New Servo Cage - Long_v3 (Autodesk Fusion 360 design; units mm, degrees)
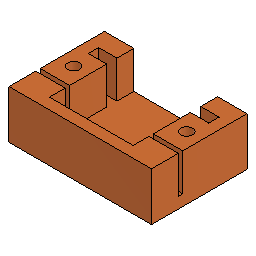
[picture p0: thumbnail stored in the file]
sketch "Sketch1" plane through (0, 0, 0) normal (0, 0, 1) x axis (1, 0, 0)
  line L1 (-14.4, -13) -> (14.4, -13)
  line L2 (-14.4, 13) -> (-14.4, -13)
  line L3 (14.4, 13) -> (-14.4, 13)
  line L4 (14.4, -13) -> (14.4, 13)
  line L5 (-14.4, 13) -> (14.4, -13)
  line L6 (14.4, 13) -> (-14.4, -13)
  line L7 (20.788, 7) -> (-24.9538, 7)
  line L8 (0, 13) -> (0, 0)
  line L9 (-19.4, 5.6) -> (19.4, 5.6)
  line L10 (-19.4, 8.4) -> (-19.4, 5.6)
  line L11 (19.4, 8.4) -> (-19.4, 8.4)
  line L12 (19.4, 5.6) -> (19.4, 8.4)
  line L13 (-19.4, 8.4) -> (19.4, 5.6)
  line L14 (19.4, 8.4) -> (-19.4, 5.6)
  line L15 (19.4, 5.6) -> (-19.4, 5.6)
  line L16 (19.4, 0.6) -> (19.4, 5.6)
  line L17 (-19.4, 0.6) -> (19.4, 0.6)
  line L18 (-19.4, 5.6) -> (-19.4, 0.6)
  line L19 (-19.4, 0) -> (0, 0)
  line L20 (19.4, 8.4) -> (-19.4, 8.4)
  line L21 (19.4, 11.4) -> (19.4, 8.4)
  line L22 (-19.4, 11.4) -> (19.4, 11.4)
  line L23 (-19.4, 8.4) -> (-19.4, 11.4)
  line L24 (-16.4, 0.6) -> (-16.4, 11.4)
  line L25 (16.4, 0.6) -> (16.4, 11.4)
  line L26 (11.4, 13) -> (-11.4, 13)
  line L27 (11.4, -10) -> (11.4, 13)
  line L28 (-11.4, -10) -> (11.4, -10)
  line L29 (-11.4, 13) -> (-11.4, -10)
  line L30 (-19.4, -13) -> (19.4, -13)
  line L31 (-19.4, 13) -> (-19.4, -13)
  line L32 (19.4, 13) -> (-19.4, 13)
  line L33 (19.4, -13) -> (19.4, 13)
  line L34 (-19.4, 13) -> (19.4, -13)
  line L35 (19.4, 13) -> (-19.4, -13)
  line L36 (19.4, -5.1) -> (-19.4, -5.1)
  line L37 (-19.4, -5.7) -> (19.4, -5.7)
  line L38 (-19.4, -4.5) -> (-19.4, -5.7)
  line L39 (19.4, -4.5) -> (-19.4, -4.5)
  line L40 (19.4, -5.7) -> (19.4, -4.5)
  line L41 (-19.4, -4.5) -> (19.4, -5.7)
  line L42 (19.4, -4.5) -> (-19.4, -5.7)
  line L43 (16.4, -13) -> (16.4, 0.6)
  line L44 (-16.4, -13) -> (-16.4, 0.6)
  circle C1 centre (-15.4, 0.6) radius 1.6
  circle C2 centre (15.4, 0.6) radius 1.6
  point P6 (0, 0)
  point P1 (0, 0)
  point P9 (0, 0)
  point P10 (0, 13)
  point P15 (0, 7)
  point P19 (-19.4, 0)
  point P23 (-16.4, 11.4)
  point P24 (-16.4, 0.6)
  point P25 (16.4, 11.4)
  point P26 (16.4, 0.6)
  point P27 (-11.4, 13)
  point P35 (0, 0)
  point P36 (-19.4, -5.1)
  point P37 (19.4, -5.1)
  point P42 (0, -5.1)
  point P43 (16.4, -13)
  point P44 (-16.4, -13)
  point P45 (-15.4, 0.6)
  point P3 (-14.4, -13)
  point P4 (-14.4, 13)
  point P2 (14.4, -13)
  point P13 (-19.4, 8.4)
  point P14 (19.4, 8.4)
  point P12 (-19.4, 5.6)
  point P18 (-19.4, 0.6)
  point P17 (19.4, 0.6)
  point P22 (-19.4, 11.4)
  point P21 (19.4, 11.4)
  point P28 (11.4, 13)
  point P30 (-11.4, -10)
  point P33 (-19.4, 13)
  point P34 (19.4, 13)
  point P32 (-19.4, -13)
  point P40 (-19.4, -4.5)
  point P41 (19.4, -4.5)
  point P39 (-19.4, -5.7)
  horizontal L1
  perpendicular L1 L2
  parallel L1 L3
  parallel L2 L4
  coincident L5 P6
  coincident L6 P6
  coincident P1 P6
  perpendicular L4 L7
  coincident P6 P9
  midpoint L3 P10
  horizontal L9
  perpendicular L9 L10
  parallel L9 L11
  parallel L10 L12
  coincident L13 P15
  coincident L14 P15
  coincident L7 P15
  coincident L8 P15
  horizontal L15
  vertical L16
  horizontal L17
  vertical L18
  coincident L18 P19
  perpendicular L18 L19
  horizontal L20
  vertical L21
  horizontal L22
  vertical L23
  coincident L22 P23
  coincident L17 P24
  perpendicular L17 L24
  symmetric L8 P23 P25
  symmetric L8 P24 P26
  horizontal L26
  vertical L27
  horizontal L28
  vertical L29
  coincident L3 P27
  horizontal L30
  perpendicular L30 L31
  parallel L30 L32
  parallel L31 L33
  coincident L34 P35
  coincident L35 P35
  coincident P9 P35
  coincident L31 P36
  coincident L33 P37
  perpendicular L33 L36
  horizontal L37
  perpendicular L37 L38
  parallel L37 L39
  parallel L38 L40
  coincident L41 P42
  coincident L42 P42
  midpoint L36 P42
  coincident L30 P43
  perpendicular L30 L43
  coincident L30 P44
  perpendicular L30 L44
  coincident L17 P45
  symmetric L8 C1 C2
  dimension "d1" distance P3 P4 = 26 (= "23 mm + 3 mm")
  dimension "d2" distance P2 P3 = 28.8 (= "22.8 mm + 6 mm")
  dimension "d3" distance L1 L7 = 20 (= "15.6 mm + d5 / 2 + 3 mm")
  dimension "d4" distance P13 P14 = 38.8 (= "d2 + 10 mm")
  dimension "d5" distance P12 P13 = 2.8
  dimension "d6" distance P12 P18 = 5
  dimension "d7" distance P17 P18 = 38.8 (= "d4")
  dimension "d13" distance P13 P22 = 3
  dimension "d14" distance P21 P22 = 38.8 (= "d4")
  dimension "d15" distance L18 L24 = 3
  dimension "d16" distance P27 P28 = 22.8
  dimension "d17" distance P27 P30 = 23
  dimension "d18" distance L2 L29 = 3
  dimension "d25" distance P33 P34 = 38.8 (= "d4")
  dimension "d26" distance P32 P33 = 26 (= "d1")
  dimension "d29" distance L28 L36 = 4.9 (= "4.4 mm + ( 1 / 2 ) * 1 mm")
  dimension "d30" distance P40 P41 = 38.8 (= "d4")
  dimension "d31" distance P39 P40 = 1.2
  dimension "d33" diameter C1 = 3.2
  dimension "d34" distance L31 P45 = 4
extrude "Extrude1" new body sketch "Sketch1" profile of L1 L2 L3 L4 L9 L10 L11 L12 L15 L16 L17 L18 L20 L21 L22 L23 L24 L25 L27 L28 L29 L30 L31 L32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 along normal blind 13.15 (= "( ( 12.3 / 2 ) * 1 mm ) + 3 mm + 4 mm")
extrude "Extrude2" add sketch "Sketch1" profile of L2 L3 L4 L9 L11 L15 L17 L20 L22 L24 L25 L26 L27 L28 L29 L31 L32 L33 L37 L38 L39 L40 L43 L44 along normal blind 3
